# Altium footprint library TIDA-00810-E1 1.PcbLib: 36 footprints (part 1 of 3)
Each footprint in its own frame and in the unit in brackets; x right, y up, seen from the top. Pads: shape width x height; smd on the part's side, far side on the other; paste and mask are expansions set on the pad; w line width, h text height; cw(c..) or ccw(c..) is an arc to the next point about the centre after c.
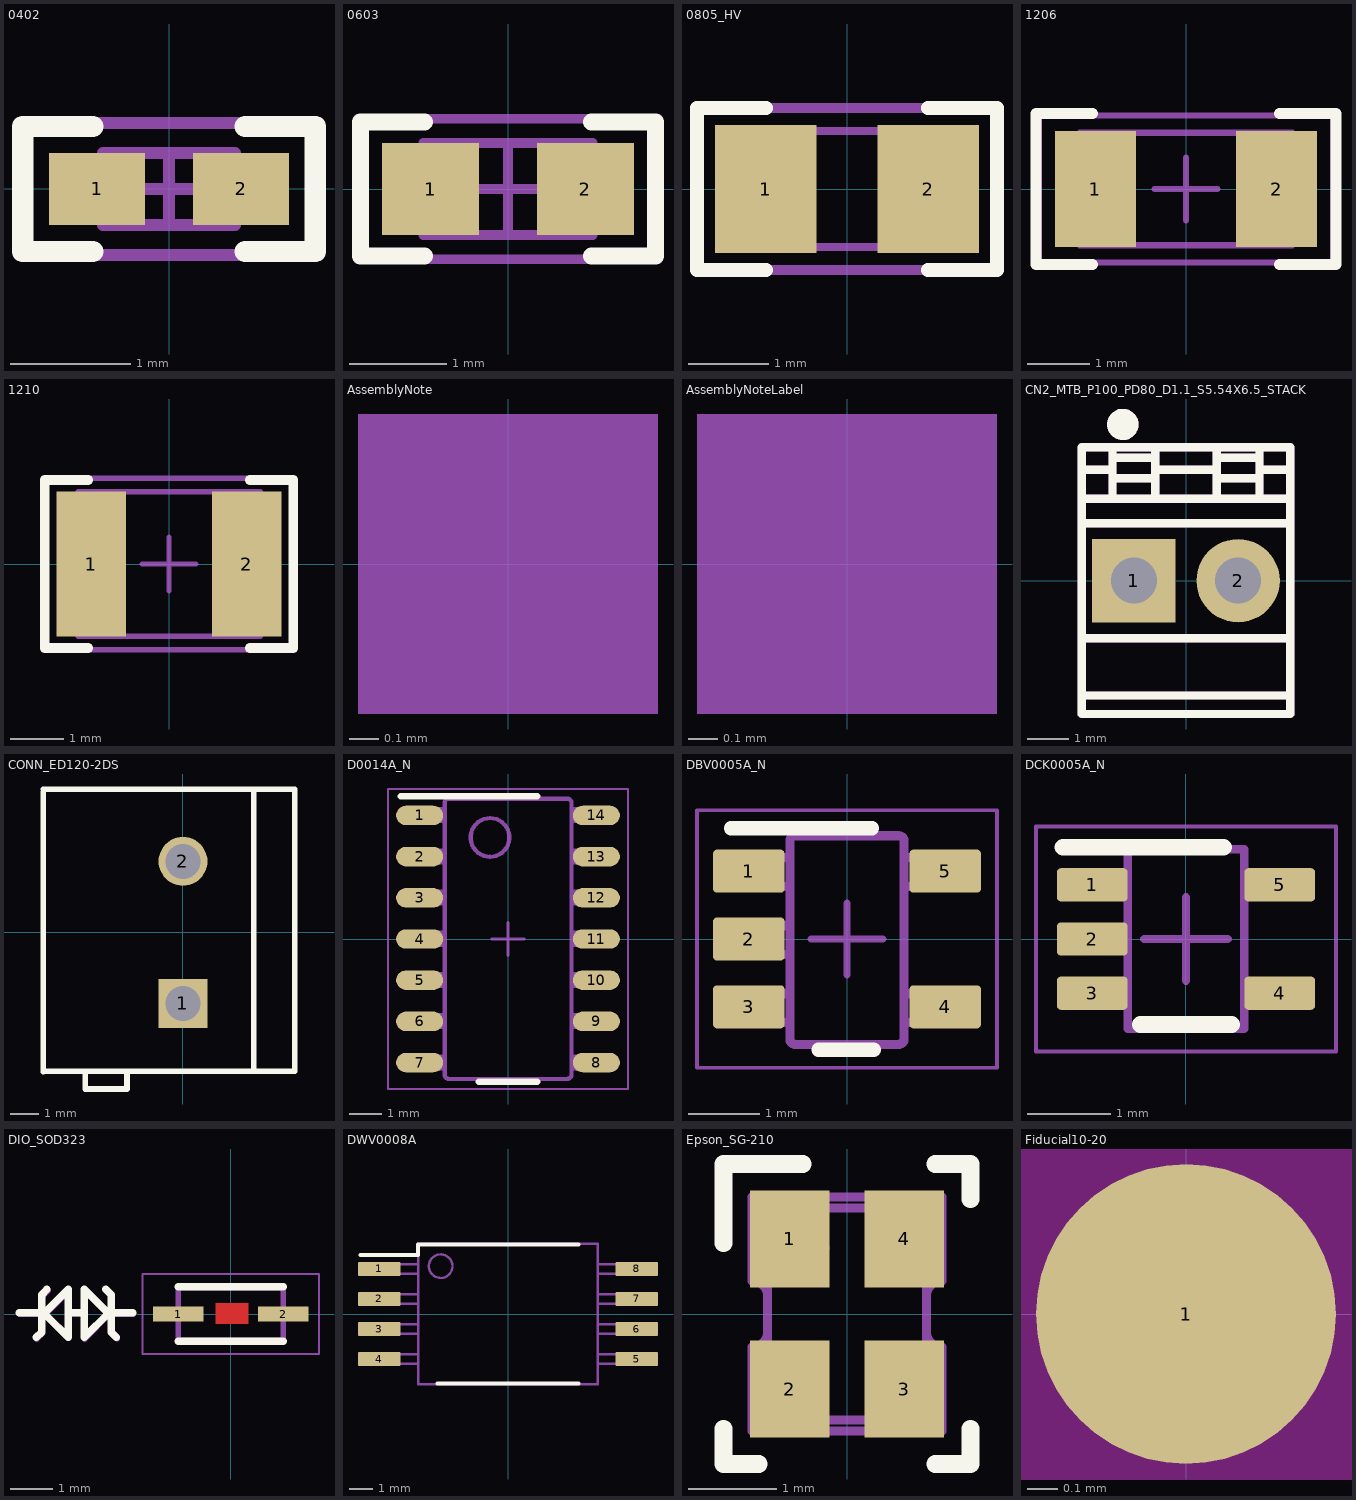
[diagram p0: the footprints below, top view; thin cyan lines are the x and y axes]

## 0402 [mm] "0402 from SM-752 data"
height 0.6
pads (2):
  rect 0.8x0.6 smd: 1(-0.6,0) 2(0.6,0)
Top Overlay:
  lines w0.178: -0.635,-0.521 -1.219,-0.521 -1.219,0.521 -0.635,0.521 ; 0.635,-0.521 1.219,-0.521 1.219,0.521 0.635,0.521
Mechanical 5:
  lines w0.1: -1.25,-0.55 -1.25,0.55 1.25,0.55 1.25,-0.55 -1.25,-0.55
  text ".Designator" at 0.762,0.254 h0.64
Mechanical 13:
  lines w0.1: -0.35,-0.3 -0.35,0.3 ; 0.35,-0.3 0.35,0.3 ; -0.55,-0.3 0.55,-0.3 0.55,0.3 -0.55,0.3 -0.55,-0.3
Mechanical 15:
  lines w0.1: -0.3,0 0.3,0 ; 0,-0.3 0,0.3 ; -1.25,-0.55 1.25,-0.55 1.25,0.55 -1.25,0.55 -1.25,-0.55
3D body: height 0.6, standoff 0, extent 0.351,-0.299 0.549,0.299
3D body: height 0.6, standoff 0, extent -0.349,-0.299 0.349,0.299
3D body: height 0.6, standoff 0, extent -0.549,-0.299 -0.351,0.299

## 0603 [mm] "0603 from SM-752 data"
height 1
pads (2):
  rect 1x0.95 smd: 1(-0.8,0) 2(0.8,0)
Top Overlay:
  lines w0.178: -0.864,-0.691 -1.524,-0.691 -1.524,0.693 -0.864,0.693 ; 0.864,-0.691 1.524,-0.691 1.524,0.693 0.864,0.693
Mechanical 5:
  lines w0.1: -1.55,-0.725 -1.55,0.725 1.55,0.725 1.55,-0.725 -1.55,-0.725
  text ".Designator" at 1.168,0.377 h0.64
Mechanical 13:
  lines w0.1: -0.55,-0.475 -0.55,0.475 ; 0.55,-0.475 0.55,0.475 ; -0.875,-0.475 0.875,-0.475 0.875,0.475 -0.875,0.475 -0.875,-0.475
Mechanical 15:
  lines w0.1: -0.475,0 0.475,0 ; 0,-0.475 0,0.475 ; -1.55,-0.725 1.55,-0.725 1.55,0.725 -1.55,0.725 -1.55,-0.725
3D body: height 1, standoff 0, extent -0.874,-0.474 -0.551,0.474
3D body: height 1, standoff 0, extent -0.549,-0.474 0.549,0.474
3D body: height 1, standoff 0, extent 0.551,-0.474 0.874,0.474

## 0805_HV [mil] "0805 with 30mil clearance between pads"
height 57.09
pads (2):
  rect 50x63 smd: 1(-40,0) 2(40,0)
Top Overlay:
  lines w7: -40,-40 -74,-40 -74,0 -74,40 -40,40 ; 40,-40 74,-40 74,0 74,40 40,40
Mechanical 5:
  lines w5: -74,-40 -74,40 74,40 74,-40 -74,-40
  text ".Designator" at -44,-12 h25
Mechanical 13:
  lines w3.94: -25.59,-28.54 -25.59,28.54 ; 25.59,-28.54 25.59,28.54 ; -43.31,-28.54 -43.31,28.54 43.31,28.54 43.31,-28.54 -43.31,-28.54
3D body: height 57.09, standoff 0, extent 25.61,-28.52 43.29,28.52
3D body: height 57.09, standoff 0, extent -25.57,-28.52 25.57,28.52
3D body: height 57.09, standoff 0, extent -43.29,-28.52 -25.61,28.52

## 1206 [mm] "1206 from SM-752 data"
height 1.35
pads (2):
  rect 1.3x1.85 smd: 1(-1.45,0) 2(1.45,0)
Top Overlay:
  lines w0.178: -1.5,-1.21 -2.4,-1.21 -2.4,1.21 -1.5,1.21 ; 1.5,-1.21 2.4,-1.21 2.4,1.21 1.5,1.21
Mechanical 5:
  lines w0.1: -1.7,-0.9 -1.7,0.9 1.7,0.9 1.7,-0.9 -1.7,-0.9
  text ".Designator" at -0.635,-0.378 h0.64
Mechanical 13:
  lines w0.1: -1.2,-0.9 -1.2,0.9 ; 1.2,-0.9 1.2,0.9 ; -1.7,-0.9 -1.7,0.9 1.7,0.9 1.7,-0.9 -1.7,-0.9
Mechanical 15:
  lines w0.1: -0.5,0 0.5,0 ; 0,-0.5 0,0.5 ; -2.35,-1.175 -2.35,1.175 2.35,1.175 2.35,-1.175 -2.35,-1.175
3D body: height 1.35, standoff 0, extent 1.201,-0.899 1.699,0.899
3D body: height 1.35, standoff 0, extent -1.199,-0.899 1.199,0.899
3D body: height 1.35, standoff 0, extent -1.699,-0.899 -1.201,0.899

## 1210 [mm] "1210 from SM-752 data"
height 1.35
pads (2):
  rect 1.3x2.7 smd: 1(-1.45,0) 2(1.45,0)
Top Overlay:
  lines w0.178: -1.511,-1.568 -2.316,-1.568 -2.316,1.568 -1.511,1.568 ; 1.511,-1.568 2.316,-1.568 2.316,1.568 1.511,1.568
Mechanical 5:
  lines w0.1: -1.7,-1.35 1.7,-1.35 1.7,1.35 -1.7,1.35 -1.7,-1.35
  text ".Designator" at -0.381,0.787 h0.64
Mechanical 13:
  lines w0.1: -1.2,-1.35 -1.2,1.35 ; 1.2,-1.35 1.2,1.35 ; -1.7,-1.35 -1.7,1.35 1.7,1.35 1.7,-1.35 -1.7,-1.35
Mechanical 15:
  lines w0.1: -0.5,0 0.5,0 ; 0,-0.5 0,0.5 ; -2.35,-1.6 -2.35,1.6 2.35,1.6 2.35,-1.6 -2.35,-1.6
3D body: height 1.35, standoff 0, extent -1.699,-1.349 -1.201,1.349
3D body: height 1.35, standoff 0, extent -1.199,-1.349 1.199,1.349
3D body: height 1.35, standoff 0, extent 1.201,-1.349 1.699,1.349

## AssemblyNote [mm] "Assembly Note"
Mechanical 5:
  rectangle: -0.508,-0.508 0.508,0.508
  text ".Comment" at 1.143,-0.508 h0.64
  text ".Designator" at -4.191,-0.508 h0.64

## AssemblyNoteLabel [mm] "Assembly Note for PCB Labels"
Mechanical 5:
  rectangle: -0.508,-0.508 0.508,0.508
  text "Install label in silkscreened box after final wash.  Text shall be 8 pt font.  Text shall be per the Label Table in the PDF schematic." at 1.143,-0.508 h0.64
  text ".Designator" at -4.191,-0.508 h0.64

## CN2_MTB_P100_PD80_D1.1_S5.54X6.5_STACK [mil]
height 118.11
pads (2):
  rect 80x80 / inner round 80 / far side rect 80x80 hole 44: 1(-50,0)
  round 80 hole 44: 2(50,0)
Top Overlay:
  circle w10: c-60.63,149.95 r5
  circle w10: c-60.63,149.95 r10
  lines w8: -100,-110.24 100,-110.24 ; -100,-55.12 100,-55.12 ; -100,55.12 100,55.12 ; -100,78.74 100,78.74 ; -100,106.3 -70.87,106.3 ; -70.47,78.74 -70.47,127.95 ; -70.47,98.43 -31.5,98.43 ; -70.47,118.11 -31.5,118.11 ; -29.53,78.74 -29.53,127.95 ; -27.56,106.3 27.56,106.3 ; 29.53,78.74 29.53,127.95 ; 31.5,98.43 66.93,98.43 ; 31.5,118.11 66.93,118.11 ; 70.47,78.74 70.47,127.95 ; 70.87,106.3 100,106.3 ; -100,-127.95 -100,127.95 100,127.95 100,-127.95 -100,-127.95
Mechanical 5:
  circle w10: c-60.63,149.95 r10
  circle w10: c-60.63,149.95 r5
  lines w8: -100,-110.24 100,-110.24 ; -100,-55.12 100,-55.12 ; -100,55.12 100,55.12 ; -100,78.74 100,78.74 ; -100,106.3 -70.87,106.3 ; -70.47,78.74 -70.47,127.95 ; -70.47,98.43 -31.5,98.43 ; -70.47,118.11 -31.5,118.11 ; -29.53,78.74 -29.53,127.95 ; -27.56,106.3 27.56,106.3 ; 29.53,78.74 29.53,127.95 ; 31.5,98.43 66.93,98.43 ; 31.5,118.11 66.93,118.11 ; 70.47,78.74 70.47,127.95 ; 70.87,106.3 100,106.3 ; -100,-127.95 100,-127.95 100,127.95 -100,127.95 -100,-127.95
  text ".designator" at -30,-15 h25

## CONN_ED120-2DS [mm] "ONSHORE"
height 13
pads (2):
  rect 1.75x1.75 hole 1.25: 1(0,-2.54)
  round 1.75 hole 1.25: 2(0,2.54)
Top Overlay:
  lines w0.2: -5,-4.985 -5,5.015 ; -5,-4.96 4,-4.96 ; -5,5.115 4,5.115 4,-4.885 ; -3.5,-4.96 -3.5,-5.6 -2,-5.6 -2,-4.96 ; 2.525,-4.95 2.525,5.05
Mechanical 5:
  lines w0.1: -5,-4.96 4,-4.96 ; -5,-4.885 -5,5.115 4,5.115 4,-4.885 ; -3.5,-4.96 -3.5,-5.6 -2,-5.6 -2,-4.96 ; 2.525,-4.875 2.525,5.125
  text ".Designator" at -1.397,0.659 h0.64
3D body: height 13, standoff 0, extent -3.5,-5.6 -2,-4.925
3D body: height 5.7, standoff 4.3, extent -0.875,-3.204 4.125,-1.81
3D body: height 5.7, standoff 4.3, extent -0.85,1.846 4.15,3.24
3D body: height 13.1, standoff -2.5, extent -0.496,2.041 0.5,3.039
3D body: height 13.1, standoff -2.5, extent -0.496,-3.039 0.5,-2.041
3D body: height 13, standoff 0, extent -5,-4.985 4,5.115

## D0014A_N [mm] "SOIC, 14-Leads, Body 8.7x3.9mm, Pitch 1.27mm, IPC Medium Density"
height 1.75
pads (14):
  oval 1.45x0.6 smd: 1(-2.725,3.81) 2(-2.725,2.54) 3(-2.725,1.27) 4(-2.725,0) 5(-2.725,-1.27) 6(-2.725,-2.54) 7(-2.725,-3.81) 8(2.725,-3.81) 9(2.725,-2.54) 10(2.725,-1.27) 11(2.725,0) 12(2.725,1.27) 13(2.725,2.54) 14(2.725,3.81)
Top Overlay:
  lines w0.2: -3.3,4.4 0.9,4.4 ; -0.9,-4.4 0.9,-4.4
Mechanical 5:
  drawing of 164 lines, arcs and shapes, not listed
  text ".Designator" at 0.647,-0.087 h0.64
Mechanical 15:
  lines w0.05: -3.7,-4.625 3.7,-4.625 3.7,4.625 -3.7,4.625 -3.7,-4.625
  lines w0.1: -0.5,0 0.5,0 ; 0,-0.5 0,0.5
3D body "D0014A.stp": height 1.6, standoff 0, extent -3.022,-4.318 3.023,4.318

## DBV0005A_N [mm] "SOT23, 5-Leads, Body 2.9x1.6mm, Pitch 0.95mm, Lead Span 2.8mm, IPC Medium Density"
height 1.45
pads (5):
  rrect17% 1x0.6 smd: 1(-1.375,0.95) 2(-1.375,0) 3(-1.375,-0.95) 4(1.375,-0.95) 5(1.375,0.95)
Top Overlay:
  lines w0.2: -1.625,1.55 0.35,1.55 ; -0.4,-1.55 0.375,-1.55
Mechanical 5:
  lines w0.127: -0.801,1.371 cw(c-0.725,1.37) -0.725,1.446 ; -0.801,1.37 -0.801,1.371 ; -0.801,1.37 -0.801,-1.399 -0.801,-1.4 ccw(c-0.725,-1.399) -0.725,-1.475 ; -0.725,-1.475 0.723,-1.475 0.724,-1.475 ccw(c0.723,-1.399) 0.799,-1.4 0.799,-1.399 0.799,1.37 ; -0.725,-1.475 -0.725,-1.475 ; -0.725,1.446 -0.725,1.446 ; -0.725,1.446 0.723,1.446 0.724,1.446 cw(c0.723,1.37) 0.799,1.371 ; 0.799,1.37 0.799,1.371 ; -1.423,-1.167 -1.423,-0.767 -1.199,-0.767 -1.105,-0.767 -1.088,-0.767 -0.835,-0.767 -0.801,-0.767 -0.801,-1.167 -0.835,-1.167 -1.088,-1.167 -1.105,-1.167 -1.199,-1.167 -1.423,-1.167 ; -1.423,-0.215 -1.423,0.186 -1.199,0.186 -1.105,0.186 -1.088,0.186 -0.835,0.186 -0.801,0.186 -0.801,-0.215 -0.835,-0.215 -1.088,-0.215 -1.105,-0.215 -1.199,-0.215 -1.423,-0.215 ; -1.423,0.738 -1.423,1.138 -1.199,1.138 -1.105,1.138 -1.088,1.138 -0.835,1.138 -0.801,1.138 -0.801,0.738 -0.835,0.738 -1.088,0.738 -1.105,0.738 -1.199,0.738 -1.423,0.738 ; 0.799,-1.167 0.834,-1.167 1.087,-1.167 1.103,-1.167 1.198,-1.167 1.422,-1.167 1.422,-0.767 1.198,-0.767 1.103,-0.767 1.087,-0.767 0.834,-0.767 0.799,-0.767 0.799,-1.167 ; 0.799,0.738 0.834,0.738 1.087,0.738 1.103,0.738 1.198,0.738 1.422,0.738 1.422,1.138 1.198,1.138 1.103,1.138 1.087,1.138 0.834,1.138 0.799,1.138 0.799,0.738
  text ".Designator" at -0.292,0.508 h0.64
Mechanical 15:
  lines w0.05: -2.1,-1.8 -2.1,1.8 2.1,1.8 2.1,-1.8 -2.1,-1.8
  lines w0.1: -0.5,0 0.5,0 ; 0,-0.5 0,0.5
3D body "DBV0005A.stp": height 1.09, standoff 0, extent -1.422,-1.461 1.423,1.46

## DCK0005A_N [mm] "SOT353, 5-Leads, Body 2x1.3mm, Pitch 0.65mm, Lead Span 2.1mm, IPC Medium Density"
height 1.1
pads (5):
  rrect25% 0.85x0.4 smd: 1(-1.125,0.65) 2(-1.125,0) 3(-1.125,-0.65) 4(1.125,-0.65) 5(1.125,0.65)
Top Overlay:
  lines w0.2: -1.475,1.1 0.45,1.1 ; -0.55,-1.025 0.55,-1.025
Mechanical 5:
  lines w0.1: -0.7,-1.075 0.7,-1.075 0.7,1.075 -0.7,1.075 -0.7,-1.075
  lines w0.127: -0.865,0.762 -0.853,0.762 ; -0.711,-0.763 -0.853,-0.763 -0.865,-0.763 -0.959,-0.763 -1.143,-0.763 -1.143,-0.538 -0.959,-0.538 -0.865,-0.538 -0.853,-0.538 -0.711,-0.538 ; -0.711,-0.113 -0.853,-0.113 -0.865,-0.113 -0.959,-0.113 -1.143,-0.113 -1.143,0.112 -0.959,0.112 -0.865,0.112 -0.853,0.112 -0.711,0.112 ; -0.711,0.537 -0.853,0.537 -0.865,0.537 -0.959,0.537 -1.143,0.537 -1.143,0.762 -0.959,0.762 -0.711,0.762 ; 0.711,-0.763 0.847,-0.763 0.859,-0.763 0.953,-0.763 1.137,-0.763 1.137,-0.538 0.953,-0.538 0.859,-0.538 0.847,-0.538 0.711,-0.538 ; 0.711,0.537 0.847,0.537 0.859,0.537 0.953,0.537 1.137,0.537 1.137,0.762 0.953,0.762 0.859,0.762 0.847,0.762 0.711,0.762
  text ".Designator" at -0.305,0.838 h0.64
Mechanical 15:
  lines w0.05: -1.8,-1.35 1.8,-1.35 1.8,1.35 -1.8,1.35 -1.8,-1.35
  lines w0.1: -0.5,0 0.5,0 ; 0,-0.5 0,0.5
3D body "DCK0005A.stp": height 0.95, standoff 0, extent -1.14,-1 1.14,1

## DIO_SOD323 [mm] "TVS DIODE, SOD323, SMT"
height 1.1
pads (2):
  rect 1.2x0.35 smd: 1(-1.25,0) 2(1.25,0)
Top Layer:
  region: -0.356,0.25 -0.357,-0.227 0.417,-0.227 0.415,0.25
Top Overlay:
  lines w0.178: -5.032,0.029 -4.532,0.029 ; -4.621,-0.557 -4.494,-0.43 -4.494,0.459 -4.367,0.586 ; -4.431,0.014 -3.859,0.586 -3.859,-0.557 -4.367,-0.049 ; -3.811,0.029 -3.534,0.029 ; -2.97,0.078 -3.478,0.586 -3.478,-0.557 -2.892,0.029 -2.332,0.029 ; -2.97,0.586 -2.843,0.459 -2.843,-0.43 -2.716,-0.557 ; -1.25,-0.65 1.25,-0.65 ; -1.25,0.65 1.25,0.65
Mechanical 5:
  lines w0.127: -5.015,-0.002 -4.515,-0.002 ; -4.615,-0.602 -4.475,-0.462 ; -4.475,-0.382 -4.475,0.418 -4.335,0.558 ; -4.415,-0.022 -3.855,0.538 -3.855,-0.582 -4.375,-0.062 ; -3.759,-0.001 -3.54,-0.002 ; -3.475,-0.602 -2.875,-0.002 ; -3.455,-0.582 -3.455,0.558 -2.855,-0.042 ; -2.95,0.563 -2.815,0.428 ; -2.83,-0.457 -2.695,-0.592 ; -2.815,-0.402 -2.815,0.398 ; -2.815,-0.002 -2.315,-0.002 ; -1.25,-0.625 1.25,-0.625 1.25,0.625 -1.25,0.625 -1.25,-0.625
  text ".Designator" at -0.787,-0.377 h0.64
Mechanical 15:
  lines w0.05: -2.1,-0.95 -2.1,0.95 2.1,0.95 2.1,-0.95 -2.1,-0.95
3D body: height 1.1, standoff 0, extent -1.25,-0.625 1.25,0.625

## DWV0008A [mm] "SOIC, 8-Leads, Body 5.95x7.6mm (max), Pitch 1.27mm"
height 2.8
pads (8):
  rrect17% 1.8x0.6 smd: 1(-5.45,1.905) 2(-5.45,0.635) 3(-5.45,-0.635) 4(-5.45,-1.905) 5(5.45,-1.905) 6(5.45,-0.635) 7(5.45,0.635) 8(5.45,1.905)
Top Overlay:
  lines w0.17: -6.25,2.5 -3.8,2.5 -3.8,2.95 2.975,2.95 ; -2.975,-2.95 2.975,-2.95
Mechanical 5:
  circle w0.1: c-2.85,2.025 r0.5
  lines w0.1: -3.805,-2.105 -5.8,-2.105 -5.8,-1.705 -3.805,-1.705 ; -3.805,-0.835 -5.8,-0.835 -5.8,-0.435 -3.805,-0.435 ; -3.805,0.435 -5.8,0.435 -5.8,0.835 -3.805,0.835 ; -3.805,1.705 -5.8,1.705 -5.8,2.105 -3.805,2.105 ; 3.805,-2.105 5.8,-2.105 5.8,-1.705 3.805,-1.705 ; 3.805,-0.835 5.8,-0.835 5.8,-0.435 3.805,-0.435 ; 3.805,0.435 5.8,0.435 5.8,0.835 3.805,0.835 ; 3.805,1.705 5.8,1.705 5.8,2.105 3.805,2.105 ; -3.8,-2.975 -3.8,2.975 3.8,2.975 3.8,-2.975 -3.8,-2.975
  text ".Designator" at -4.318,-4.064 h0.64
3D body "DWV0008A.stp": height 2.67, standoff -0.03, extent -5.768,-2.925 5.768,2.925

## Epson_SG-210 [mm] "SMD, 2-Leads, Body 2x2.5mm"
height 0.9
pads (4):
  rect 0.9x1.1 smd: 1(-0.65,0.85) 2(-0.65,-0.85) 3(0.65,-0.85) 4(0.65,0.85)
Top Overlay:
  lines w0.2: -1.4,-1.3 -1.4,-1.7 -1,-1.7 ; -1.4,0.8 -1.4,1.7 -0.5,1.7 ; 1,-1.7 1.4,-1.7 1.4,-1.3 ; 1,1.7 1.4,1.7 1.4,1.3
Mechanical 5:
  circle w0.1: c-0.5,0.75 r0.25
  lines w0.1: -1.075,-1.325 -1.075,-0.375 ccw(c-1.075,-0.2) -0.9,-0.2 -0.9,0.2 ccw(c-1.075,0.2) -1.075,0.375 -1.075,1.325 1.075,1.325 1.075,0.375 ccw(c1.075,0.2) 0.9,0.2 0.9,-0.2 ccw(c1.075,-0.2) 1.075,-0.375 1.075,-1.325 -1.075,-1.325 ; -0.9,-1 ccw(c-0.7,-1) -0.7,-1.2 0.7,-1.2 ccw(c0.7,-1) 0.9,-1 0.9,1 ccw(c0.7,1) 0.7,1.2 -0.7,1.2 ccw(c-0.7,1) -0.9,1 -0.9,-1
  text ".Designator" at -0.254,0.254 h0.64
3D body: height 0.91, standoff 0.9, extent -0.7,0.55 -0.3,0.95
3D body: height 0.8, standoff 0, extent -1.076,-1.326 1.076,1.326
3D body: height 0.9, standoff 0.8, extent -0.9,-1.199 0.9,1.199

## Fiducial10-20 [mm]
height 2.65
pads (1):
  round 1 smd mask+0.5: 1(0,0)
Top Layer keep-out:
  circle w1.178: c0,0 r0.5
